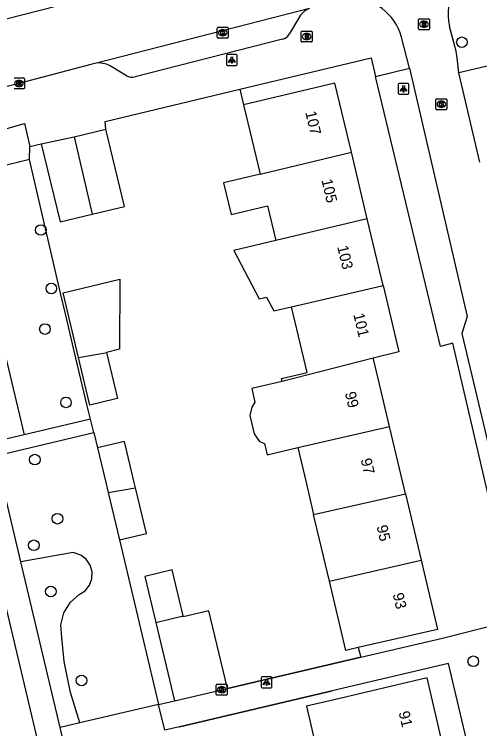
# Model space of a CAD drawing. Extents: x 157793 to 159380, y 380882 to 382313.
# Drawn here: x 158635.1 to 158677.9, y 381227.4 to 381293.1 of the extents above; entities that cross this region are included whole.
import ezdxf

# ---------------------------------------------------------------- set-up
doc = ezdxf.new("R2010")
doc.units = 0
for name, color, linetype in [('IMGEO_Boom', 7, 'Continuous'), ('IMGEO_Brandkraan', 7, 'Continuous'), ('IMGEO_Fietspad_open', 7, 'Continuous'), ('IMGEO_Groenvoorziening', 7, 'Continuous'), ('IMGEO_Kolk', 7, 'Continuous'), ('IMGEO_Lichtpunt', 7, 'Continuous'), ('IMGEO_Muur', 7, 'Continuous'), ('IMGEO_Pand', 7, 'Continuous'), ('IMGEO_Pand_nummerreeks', 7, 'Continuous'), ('IMGEO_Rijbaan_lokaal_gesloten', 7, 'Continuous'), ('IMGEO_Rijbaan_lokaal_open', 7, 'Continuous'), ('IMGEO_Rioolput', 7, 'Continuous'), ('IMGEO_Voetpad_op_trap', 7, 'Continuous'), ('IMGEO_Voetpad_open', 7, 'Continuous')]:
    doc.layers.add(name, color=color, linetype=linetype)

msp = doc.modelspace()

# ---------------------------------------------------------------- linework, layer by layer
at = {"layer": 'IMGEO_Boom'}
for centre in [(158676.283, 381290.53), (158637.544, 381273.251), (158638.514, 381267.861), (158637.926, 381264.134), (158639.861, 381257.382), (158636.999, 381252.118), (158639.083, 381246.68), (158636.907, 381244.233), (158638.472, 381239.977), (158677.333, 381233.559), (158641.286, 381231.795)]:
    msp.add_circle(centre, 0.489, dxfattribs=at)
at = {"layer": 'IMGEO_Brandkraan'}
for p, q in [((158661.502, 381290.627), (158661.502, 381291.479)), ((158661.577, 381291.553), (158662.429, 381291.553)), ((158661.99, 381291.333), (158662.015, 381291.333)), ((158662.503, 381291.479), (158662.503, 381290.627)), ((158662.429, 381290.553), (158661.577, 381290.553)), ((158662.013, 381290.773), (158661.988, 381290.773))]:
    msp.add_line(p, q, dxfattribs=at)
for points in [[(158661.502, 381290.627), (158661.502, 381291.479)], [(158661.577, 381291.553), (158662.429, 381291.553)], [(158661.85, 381291.253), (158661.85, 381290.853), (158662.063, 381290.853)], [(158662.081, 381291.253), (158661.85, 381291.253)], [(158662.029, 381291.172), (158661.975, 381291.172), (158661.975, 381291.096)], [(158661.975, 381291.096), (158662.028, 381291.096)], [(158662.037, 381291.02), (158661.975, 381291.02), (158661.975, 381290.939)], [(158662.503, 381291.479), (158662.503, 381290.627)], [(158662.429, 381290.553), (158661.577, 381290.553)], [(158661.975, 381290.939), (158662.037, 381290.939)]]:
    msp.add_lwpolyline(points, dxfattribs=at)
for centre, radius, start, end in [((158661.579, 381291.477), 0.0765, 91.55205, 178.44795), ((158661.579, 381291.477), 0.0765, 91.55205, 178.44795), ((158662.03, 381291.134), 0.0379, 267.82845, 90.93552), ((158662.038, 381290.979), 0.0404, 269.87594, 90.50774), ((158662.085, 381291.108), 0.145, 59.4692, 91.53667), ((158662.11, 381291.155), 0.0922, 285.51372, 58.15012), ((158662.115, 381290.963), 0.105, 301.31148, 78.98903), ((158662.427, 381291.477), 0.0765, 1.55205, 88.44795), ((158662.427, 381291.477), 0.0765, 1.55205, 88.44795), ((158661.579, 381290.629), 0.0765, 181.55205, 268.44795), ((158661.579, 381290.629), 0.0765, 181.55205, 268.44795), ((158662.069, 381291.104), 0.251, 268.66757, 293.53466), ((158662.427, 381290.629), 0.0765, 271.55205, 358.44795), ((158662.427, 381290.629), 0.0765, 271.55205, 358.44795)]:
    msp.add_arc(centre, radius, start, end, dxfattribs=at)
for centre, major_axis, ratio, start_param, end_param in [((158661.989, 381291.053), (-0.387, 0.002), 0.722429, 4.712389, 7.853982), ((158662.014, 381291.053), (-0.39, 0.002), 0.717154, 1.570796, 4.712389)]:
    msp.add_ellipse(centre, major_axis=major_axis, ratio=ratio, start_param=start_param, end_param=end_param, dxfattribs=at)
at = {"layer": 'IMGEO_Fietspad_open'}
msp.add_lwpolyline([(158653.459, 381158.427), (158653.459, 381158.428), (158652.71, 381161.57), (158651.138, 381168.163), (158650.385, 381171.319), (158649.514, 381174.661), (158645.033, 381193.65), (158637.662, 381224.561), (158632.206, 381247.49), (158631.61, 381250), (158626.887, 381270.801), (158625.632, 381276.047)], dxfattribs=at)
at = {"layer": 'IMGEO_Groenvoorziening'}
for points in [[(158636.517, 381279.745), (158636.534, 381280.932)], [(158636.517, 381279.745), (158633.485, 381278.994), (158632.723, 381278.67), (158632.114, 381278.242), (158631.629, 381277.72), (158631.278, 381277.098), (158631.215, 381276.929), (158631.029, 381276.015), (158631.21, 381274.565), (158636.012, 381254.407)], [(158642.116, 381255.85), (158641.816, 381257.081), (158640.774, 381261.468), (158639.804, 381265.55), (158639.359, 381267.423), (158636.517, 381279.745)], [(158642.419, 381254.605), (158642.761, 381253.199)], [(158644.774, 381244.722), (158648.376, 381229.59)], [(158641.127, 381227.899), (158640.267, 381230.684), (158639.704, 381233.543), (158639.477, 381235.747), (158639.395, 381236.898), (158639.672, 381238.019), (158640.282, 381238.999), (158641.085, 381239.693), (158641.617, 381240.049), (158642.013, 381240.553), (158642.234, 381241.154), (158642.259, 381241.794), (158642.084, 381242.41), (158641.728, 381242.943), (158641.224, 381243.339), (158640.509, 381243.579), (158635.712, 381242.7)]]:
    msp.add_lwpolyline(points, dxfattribs=at)
at = {"layer": 'IMGEO_Kolk'}
for p, q in [((158653.784, 381290.986), (158653.784, 381291.838)), ((158653.859, 381291.912), (158654.711, 381291.912)), ((158654.272, 381291.692), (158654.297, 381291.692)), ((158654.785, 381291.838), (158654.785, 381290.986)), ((158654.295, 381291.132), (158654.27, 381291.132)), ((158654.711, 381290.912), (158653.859, 381290.912)), ((158635.106, 381287.241), (158635.958, 381287.241)), ((158635.519, 381287.021), (158635.544, 381287.021)), ((158636.032, 381287.167), (158636.032, 381286.315)), ((158635.542, 381286.461), (158635.517, 381286.461)), ((158635.958, 381286.241), (158635.106, 381286.241)), ((158673.896, 381284.398), (158673.896, 381285.25)), ((158673.971, 381285.324), (158674.823, 381285.324)), ((158674.384, 381285.104), (158674.409, 381285.104)), ((158674.897, 381285.25), (158674.897, 381284.398)), ((158674.407, 381284.544), (158674.382, 381284.544)), ((158674.823, 381284.324), (158673.971, 381284.324)), ((158653.677, 381230.517), (158653.677, 381231.369)), ((158653.752, 381231.443), (158654.604, 381231.443)), ((158654.165, 381231.223), (158654.19, 381231.223)), ((158654.678, 381231.369), (158654.678, 381230.517)), ((158654.188, 381230.663), (158654.163, 381230.663)), ((158654.604, 381230.443), (158653.752, 381230.443))]:
    msp.add_line(p, q, dxfattribs=at)
for points in [[(158653.784, 381290.986), (158653.784, 381291.838)], [(158653.859, 381291.912), (158654.711, 381291.912)], [(158654.105, 381291.612), (158654.228, 381291.612), (158654.228, 381291.461), (158654.358, 381291.612), (158654.522, 381291.612), (158654.376, 381291.461), (158654.529, 381291.212), (158654.377, 381291.212), (158654.292, 381291.376), (158654.228, 381291.309), (158654.228, 381291.212), (158654.105, 381291.212), (158654.105, 381291.612)], [(158654.785, 381291.838), (158654.785, 381290.986)], [(158654.711, 381290.912), (158653.859, 381290.912)], [(158635.106, 381287.241), (158635.958, 381287.241)], [(158636.032, 381287.167), (158636.032, 381286.315)], [(158635.352, 381286.941), (158635.475, 381286.941), (158635.475, 381286.79), (158635.605, 381286.941), (158635.769, 381286.941), (158635.623, 381286.79), (158635.776, 381286.541), (158635.624, 381286.541), (158635.539, 381286.705), (158635.475, 381286.638), (158635.475, 381286.541), (158635.352, 381286.541), (158635.352, 381286.941)], [(158635.958, 381286.241), (158635.106, 381286.241)], [(158673.896, 381284.398), (158673.896, 381285.25)], [(158673.971, 381285.324), (158674.823, 381285.324)], [(158674.897, 381285.25), (158674.897, 381284.398)], [(158674.217, 381285.024), (158674.34, 381285.024), (158674.34, 381284.873), (158674.47, 381285.024), (158674.634, 381285.024), (158674.488, 381284.873), (158674.641, 381284.624), (158674.489, 381284.624), (158674.404, 381284.788), (158674.34, 381284.721), (158674.34, 381284.624), (158674.217, 381284.624), (158674.217, 381285.024)], [(158674.823, 381284.324), (158673.971, 381284.324)], [(158653.677, 381230.517), (158653.677, 381231.369)], [(158653.752, 381231.443), (158654.604, 381231.443)], [(158653.998, 381231.143), (158654.121, 381231.143), (158654.121, 381230.992), (158654.251, 381231.143), (158654.415, 381231.143), (158654.269, 381230.992), (158654.422, 381230.743), (158654.27, 381230.743), (158654.185, 381230.907), (158654.121, 381230.84), (158654.121, 381230.743), (158653.998, 381230.743), (158653.998, 381231.143)], [(158654.678, 381231.369), (158654.678, 381230.517)], [(158654.604, 381230.443), (158653.752, 381230.443)]]:
    msp.add_lwpolyline(points, dxfattribs=at)
for centre, start, end in [((158653.861, 381291.836), 91.55205, 178.44795), ((158653.861, 381291.836), 91.55205, 178.44795), ((158654.709, 381291.836), 1.55205, 88.44795), ((158654.709, 381291.836), 1.55205, 88.44795), ((158653.861, 381290.988), 181.55205, 268.44795), ((158653.861, 381290.988), 181.55205, 268.44795), ((158654.709, 381290.988), 271.55205, 358.44795), ((158654.709, 381290.988), 271.55205, 358.44795), ((158635.956, 381287.165), 1.55205, 88.44795), ((158635.956, 381287.165), 1.55205, 88.44795), ((158635.956, 381286.317), 271.55205, 358.44795), ((158635.956, 381286.317), 271.55205, 358.44795), ((158673.973, 381285.248), 91.55205, 178.44795), ((158673.973, 381285.248), 91.55205, 178.44795), ((158674.821, 381285.248), 1.55205, 88.44795), ((158674.821, 381285.248), 1.55205, 88.44795), ((158673.973, 381284.4), 181.55205, 268.44795), ((158673.973, 381284.4), 181.55205, 268.44795), ((158674.821, 381284.4), 271.55205, 358.44795), ((158674.821, 381284.4), 271.55205, 358.44795), ((158653.754, 381231.367), 91.55205, 178.44795), ((158653.754, 381231.367), 91.55205, 178.44795), ((158654.602, 381231.367), 1.55205, 88.44795), ((158654.602, 381231.367), 1.55205, 88.44795), ((158653.754, 381230.519), 181.55205, 268.44795), ((158653.754, 381230.519), 181.55205, 268.44795), ((158654.602, 381230.519), 271.55205, 358.44795), ((158654.602, 381230.519), 271.55205, 358.44795)]:
    msp.add_arc(centre, 0.0765, start, end, dxfattribs=at)
for centre, major_axis, ratio, start_param, end_param in [((158654.271, 381291.412), (-0.387, 0.002), 0.722429, 4.712389, 7.853982), ((158654.296, 381291.412), (-0.39, 0.002), 0.717154, 1.570796, 4.712389), ((158635.518, 381286.741), (-0.387, 0.002), 0.722429, 4.712389, 7.853982), ((158635.543, 381286.741), (-0.39, 0.002), 0.717154, 1.570796, 4.712389), ((158674.383, 381284.824), (-0.387, 0.002), 0.722429, 4.712389, 7.853982), ((158674.408, 381284.824), (-0.39, 0.002), 0.717154, 1.570796, 4.712389), ((158654.164, 381230.943), (-0.387, 0.002), 0.722429, 4.712389, 7.853982), ((158654.189, 381230.943), (-0.39, 0.002), 0.717154, 1.570796, 4.712389)]:
    msp.add_ellipse(centre, major_axis=major_axis, ratio=ratio, start_param=start_param, end_param=end_param, dxfattribs=at)
at = {"layer": 'IMGEO_Lichtpunt'}
for p, q in [((158654.624, 381289.298), (158654.624, 381288.491)), ((158654.624, 381289.298), (158654.624, 381288.491)), ((158655.526, 381289.393), (158654.718, 381289.393)), ((158655.526, 381289.393), (158654.718, 381289.393)), ((158655.62, 381288.491), (158655.62, 381289.298)), ((158655.62, 381288.491), (158655.62, 381289.298)), ((158654.718, 381288.397), (158655.526, 381288.397)), ((158654.718, 381288.397), (158655.526, 381288.397)), ((158670.418, 381286.642), (158670.418, 381285.835)), ((158670.418, 381286.642), (158670.418, 381285.835)), ((158671.32, 381286.737), (158670.512, 381286.737)), ((158671.32, 381286.737), (158670.512, 381286.737)), ((158671.414, 381285.835), (158671.414, 381286.642)), ((158671.414, 381285.835), (158671.414, 381286.642)), ((158670.512, 381285.741), (158671.32, 381285.741)), ((158670.512, 381285.741), (158671.32, 381285.741)), ((158657.817, 381232.028), (158657.817, 381231.221)), ((158657.817, 381232.028), (158657.817, 381231.221)), ((158658.719, 381232.123), (158657.911, 381232.123)), ((158658.719, 381232.123), (158657.911, 381232.123)), ((158658.813, 381231.221), (158658.813, 381232.028)), ((158658.813, 381231.221), (158658.813, 381232.028)), ((158657.911, 381231.127), (158658.719, 381231.127)), ((158657.911, 381231.127), (158658.719, 381231.127))]:
    msp.add_line(p, q, dxfattribs=at)
for points in [[(158654.998, 381288.962), (158655.037, 381288.934), (158654.849, 381288.672), (158654.811, 381288.699), (158654.998, 381288.962)], [(158655.1, 381288.914), (158655.147, 381288.914), (158655.147, 381288.592), (158655.1, 381288.592), (158655.1, 381288.914)], [(158655.21, 381288.934), (158655.248, 381288.961), (158655.435, 381288.699), (158655.396, 381288.671), (158655.21, 381288.934)], [(158670.792, 381286.306), (158670.831, 381286.278), (158670.643, 381286.016), (158670.605, 381286.043), (158670.792, 381286.306)], [(158670.894, 381286.258), (158670.941, 381286.258), (158670.941, 381285.936), (158670.894, 381285.936), (158670.894, 381286.258)], [(158671.004, 381286.278), (158671.042, 381286.305), (158671.229, 381286.043), (158671.19, 381286.015), (158671.004, 381286.278)], [(158658.191, 381231.692), (158658.23, 381231.664), (158658.042, 381231.402), (158658.004, 381231.429), (158658.191, 381231.692)], [(158658.293, 381231.644), (158658.34, 381231.644), (158658.34, 381231.322), (158658.293, 381231.322), (158658.293, 381231.644)], [(158658.403, 381231.664), (158658.441, 381231.691), (158658.628, 381231.429), (158658.589, 381231.401), (158658.403, 381231.664)]]:
    msp.add_lwpolyline(points, dxfattribs=at)
for centre in [(158655.123, 381289.096), (158670.917, 381286.44), (158658.316, 381231.826)]:
    msp.add_circle(centre, 0.0994, dxfattribs=at)
for centre, start, end in [((158654.718, 381289.298), 90, 180), ((158654.718, 381289.298), 90, 180), ((158655.526, 381289.298), 0, 90), ((158655.526, 381289.298), 0, 90), ((158654.718, 381288.491), 180, 270), ((158654.718, 381288.491), 180, 270), ((158655.526, 381288.491), 270, 0), ((158655.526, 381288.491), 270, 360), ((158670.512, 381286.642), 90, 180), ((158670.512, 381286.642), 90, 180), ((158671.32, 381286.642), 0, 90), ((158671.32, 381286.642), 0, 90), ((158670.512, 381285.835), 180, 270), ((158670.512, 381285.835), 180, 270), ((158671.32, 381285.835), 270, 0), ((158671.32, 381285.835), 270, 360), ((158657.911, 381232.028), 90, 180), ((158657.911, 381232.028), 90, 180), ((158658.719, 381232.028), 0, 90), ((158658.719, 381232.028), 0, 90), ((158657.911, 381231.221), 180, 270), ((158657.911, 381231.221), 180, 270), ((158658.719, 381231.221), 270, 0), ((158658.719, 381231.221), 270, 360)]:
    msp.add_arc(centre, 0.0946, start, end, dxfattribs=at)
at = {"layer": 'IMGEO_Muur'}
for points in [[(158655.862, 381286.202), (158656.203, 381284.765)], [(158643.537, 381282.528), (158643.451, 381283.23)], [(158666.748, 381234.815), (158666.978, 381233.931)], [(158666.978, 381233.931), (158654.705, 381231.068)], [(158650.313, 381227.528), (158664.347, 381230.829)]]:
    msp.add_lwpolyline(points, dxfattribs=at)
at = {"layer": 'IMGEO_Pand'}
for points in [[(158666.112, 381280.411), (158664.603, 381286.761), (158656.203, 381284.765), (158657.715, 381278.401)], [(158640.612, 381281.833), (158643.537, 381282.528)], [(158642.282, 381274.703), (158645.23, 381275.403), (158643.537, 381282.528)], [(158637.582, 381281.188), (158640.612, 381281.833)], [(158640.612, 381281.833), (158642.282, 381274.703)], [(158637.582, 381281.188), (158639.327, 381274.001), (158642.282, 381274.703)], [(158657.715, 381278.401), (158666.112, 381280.411)], [(158667.569, 381274.275), (158666.112, 381280.411)], [(158657.715, 381278.401), (158654.346, 381277.601), (158655.043, 381274.668), (158658.411, 381275.469), (158659.166, 381272.292)], [(158667.569, 381274.275), (158659.166, 381272.292)], [(158669.025, 381268.149), (158667.569, 381274.275)], [(158659.166, 381272.292), (158655.29, 381271.377), (158657.63, 381266.915), (158658.32, 381267.076), (158658.989, 381265.801), (158660.617, 381266.181)], [(158641.021, 381261.511), (158639.602, 381267.481), (158644.827, 381268.722), (158644.799, 381262.28), (158643.586, 381261.981)], [(158660.617, 381266.181), (158669.025, 381268.149)], [(158669.025, 381268.149), (158670.475, 381262.043), (158668.123, 381261.447)], [(158659.736, 381259.321), (158659.676, 381259.573), (158662.053, 381260.138), (158660.617, 381266.181)], [(158643.586, 381261.981), (158644.593, 381257.741), (158644.312, 381257.674), (158642.059, 381257.139), (158641.021, 381261.511)], [(158641.021, 381261.511), (158643.307, 381261.912), (158643.586, 381261.981)], [(158668.123, 381261.447), (158659.736, 381259.321)], [(158669.612, 381255.177), (158668.568, 381259.572), (158668.175, 381261.227), (158668.123, 381261.447)], [(158659.736, 381259.321), (158656.948, 381258.659), (158657.244, 381257.415), (158656.949, 381256.935), (158656.787, 381256.174), (158657.187, 381254.491), (158657.657, 381253.795), (158658.11, 381253.598), (158658.359, 381252.554), (158661.185, 381253.225)], [(158661.185, 381253.225), (158669.612, 381255.177)], [(158671.085, 381248.972), (158670.841, 381250), (158669.612, 381255.177)], [(158646.255, 381249.524), (158646.142, 381250), (158645.242, 381253.788), (158642.761, 381253.199)], [(158642.761, 381253.199), (158643.521, 381250), (158643.737, 381249.089)], [(158661.185, 381253.225), (158661.951, 381250), (158662.641, 381247.079)], [(158643.737, 381249.089), (158646.255, 381249.524)], [(158643.737, 381249.089), (158644.774, 381244.722)], [(158644.774, 381244.722), (158647.255, 381245.311), (158646.255, 381249.524)], [(158662.641, 381247.079), (158671.085, 381248.972)], [(158671.085, 381248.972), (158672.533, 381242.875)], [(158664.092, 381240.932), (158662.641, 381247.079)], [(158672.533, 381242.875), (158674.047, 381236.496), (158666.748, 381234.815), (158665.599, 381234.55), (158664.092, 381240.932)], [(158664.092, 381240.932), (158672.533, 381242.875)], [(158650.631, 381237.747), (158649.63, 381241.963), (158647.118, 381241.367), (158648.124, 381237.133)], [(158648.124, 381237.133), (158650.631, 381237.747)], [(158654.705, 381231.068), (158653.009, 381238.207), (158650.655, 381237.648), (158650.631, 381237.747)], [(158648.124, 381237.133), (158649.835, 381229.931)], [(158674.572, 381225.676), (158673.077, 381232.032), (158664.537, 381230.023), (158661.98, 381229.422), (158663.474, 381223.073), (158666.031, 381223.673)], [(158649.835, 381229.931), (158654.705, 381231.068)]]:
    msp.add_lwpolyline(points, dxfattribs=at)
at = {"layer": 'IMGEO_Rijbaan_lokaal_gesloten'}
for points in [[(158632.774, 381292.27), (158662.382, 381299.863)], [(158662.278, 381293.627), (158642.781, 381288.621)], [(158642.781, 381288.621), (158642.14, 381288.482), (158635.532, 381286.741), (158634.315, 381286.423)]]:
    msp.add_lwpolyline(points, dxfattribs=at)
at = {"layer": 'IMGEO_Rijbaan_lokaal_open'}
for points in [[(158675.996, 381287.714), (158675.862, 381289.109), (158675.767, 381289.723), (158675.128, 381291.98)], [(158671.453, 381288.156), (158670.72, 381290.986)], [(158671.453, 381288.156), (158676.756, 381265.295), (158676.268, 381263.721), (158683.168, 381234.722)], [(158677.936, 381279.502), (158675.996, 381287.714)]]:
    msp.add_lwpolyline(points, dxfattribs=at)
for centre, radius, start, end in [((158680.015, 381293.068), 5.006, 104.85682, 192.55267), ((158666.049, 381289.747), 4.833, 14.85765, 91.79137)]:
    msp.add_arc(centre, radius, start, end, dxfattribs=at)
at = {"layer": 'IMGEO_Rioolput'}
for p, q in [((158672.295, 381291.758), (158672.295, 381292.61)), ((158672.37, 381292.684), (158673.222, 381292.684)), ((158672.783, 381292.464), (158672.808, 381292.464)), ((158673.296, 381292.61), (158673.296, 381291.758)), ((158673.222, 381291.684), (158672.37, 381291.684)), ((158672.806, 381291.904), (158672.781, 381291.904))]:
    msp.add_line(p, q, dxfattribs=at)
for points in [[(158672.295, 381291.758), (158672.295, 381292.61)], [(158672.37, 381292.684), (158673.222, 381292.684)], [(158672.884, 381292.382), (158672.632, 381292.384), (158672.632, 381291.984)], [(158672.81, 381292.303), (158672.756, 381292.303), (158672.756, 381292.222)], [(158673.296, 381292.61), (158673.296, 381291.758)], [(158673.222, 381291.684), (158672.37, 381291.684)], [(158672.632, 381291.984), (158672.756, 381291.984), (158672.756, 381292.146), (158672.767, 381292.146)], [(158672.756, 381292.222), (158672.808, 381292.222)], [(158672.814, 381292.117), (158672.885, 381291.984), (158673.025, 381291.984), (158672.96, 381292.11)]]:
    msp.add_lwpolyline(points, dxfattribs=at)
for centre, radius, start, end in [((158672.372, 381292.608), 0.0765, 91.55205, 178.44795), ((158672.372, 381292.608), 0.0765, 91.55205, 178.44795), ((158672.816, 381292.207), 0.0964, 77.00612, 93.18647), ((158672.83, 381292.264), 0.0378, 276.66336, 79.67722), ((158672.883, 381292.272), 0.109, 350.36119, 89.41601), ((158673.22, 381292.608), 0.0765, 1.55205, 88.44795), ((158673.22, 381292.608), 0.0765, 1.55205, 88.44795), ((158672.372, 381291.76), 0.0765, 181.55205, 268.44795), ((158672.372, 381291.76), 0.0765, 181.55205, 268.44795), ((158672.766, 381292.093), 0.0533, 26.02933, 88.69889), ((158672.792, 381292.411), 0.19, 274.7715, 282.96867), ((158672.881, 381292.272), 0.112, 277.58423, 350.98172), ((158672.865, 381292.057), 0.108, 29.51342, 73.79051), ((158673.22, 381291.76), 0.0765, 271.55205, 358.44795), ((158673.22, 381291.76), 0.0765, 271.55205, 358.44795)]:
    msp.add_arc(centre, radius, start, end, dxfattribs=at)
for centre, major_axis, ratio, start_param, end_param in [((158672.782, 381292.184), (-0.387, 0.002), 0.722429, 4.712389, 7.853982), ((158672.807, 381292.184), (-0.39, 0.002), 0.717154, 1.570796, 4.712389)]:
    msp.add_ellipse(centre, major_axis=major_axis, ratio=ratio, start_param=start_param, end_param=end_param, dxfattribs=at)
at = {"layer": 'IMGEO_Voetpad_op_trap'}
for points in [[(158648.376, 381229.59), (158641.127, 381227.899)], [(158641.127, 381227.899), (158639.332, 381227.48)]]:
    msp.add_lwpolyline(points, dxfattribs=at)
at = {"layer": 'IMGEO_Voetpad_open'}
for points in [[(158661.238, 381292.727), (158660.388, 381291.259)], [(158659.767, 381290.809), (158646.212, 381287.346)], [(158643.537, 381282.528), (158643.451, 381283.23), (158655.862, 381286.202), (158667.943, 381289.095), (158668.346, 381287.373)], [(158679.54, 381288.53), (158675.996, 381287.714)], [(158645.422, 381287.441), (158644.013, 381288.301)], [(158668.346, 381287.373), (158671.453, 381288.156)], [(158654.705, 381231.068), (158666.978, 381233.931), (158674.495, 381235.697), (158681.372, 381237.445), (158675.438, 381262.839), (158674.305, 381262.524), (158668.346, 381287.373)], [(158632.674, 381282.091), (158636.033, 381283.058), (158636.534, 381280.932)], [(158636.534, 381280.932), (158637.582, 381281.188)], [(158636.012, 381254.407), (158633.091, 381253.716), (158628.55, 381273.599), (158628.189, 381275.277)], [(158642.116, 381255.85), (158636.012, 381254.407)], [(158642.419, 381254.605), (158642.116, 381255.85)], [(158635.712, 381242.7), (158633.976, 381250), (158633.39, 381252.463), (158642.419, 381254.605)], [(158639.332, 381227.48), (158635.712, 381242.7)], [(158679.171, 381220.243), (158678.197, 381220.001), (158675.05, 381233.346), (158664.347, 381230.829), (158650.313, 381227.528), (158648.943, 381227.206)], [(158648.376, 381229.59), (158649.835, 381229.931)], [(158648.943, 381227.206), (158648.376, 381229.59)], [(158639.885, 381225.076), (158639.332, 381227.48)]]:
    msp.add_lwpolyline(points, dxfattribs=at)
for centre, radius, start, end in [((158662.964, 381291.783), 1.968, 110.41564, 151.32917), ((158659.586, 381291.712), 0.921, 281.31104, 330.54597), ((158642.873, 381286.445), 2.178, 58.44637, 92.43308), ((158645.963, 381288.609), 1.288, 245.14416, 281.14169)]:
    msp.add_arc(centre, radius, start, end, dxfattribs=at)

# ---------------------------------------------------------------- texts
at = {"layer": 'IMGEO_Pand_nummerreeks'}
for s, rotation, p in [('107', 283.36437, (158661.869, 381284.081)), ('105', 283.36437, (158663.352, 381277.837)), ('103', 283.36117, (158664.807, 381271.707)), ('101', 283.36117, (158666.287, 381265.48)), ('99', 283.34971, (158665.51, 381258.248)), ('97', 283.34547, (158666.964, 381252.121)), ('95', 283.35989, (158668.424, 381245.969)), ('93', 283.36861, (158669.907, 381239.731)), ('91', 283.23511, (158670.453, 381228.858))]:
    msp.add_text(s, height=1, rotation=rotation, dxfattribs=at).set_placement(p)

doc.saveas('drawing.dxf')
